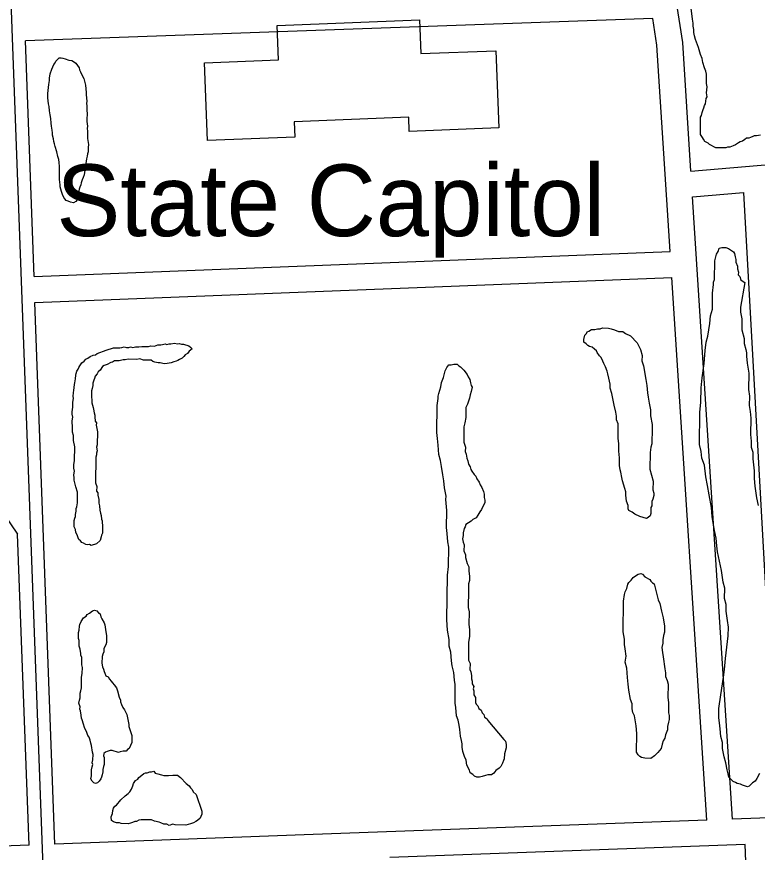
# Model space of a CAD drawing. Extents: x 3313447 to 3351316, y 703786 to 729172.
# Drawn here: x 3326436 to 3327294, y 710857 to 711825 of the extents above; entities that cross this region are included whole.
import ezdxf

# ---------------------------------------------------------------- set-up
doc = ezdxf.new("R2010")
doc.units = 0
for name, color, linetype in [('V-BLDG-IDEN', 7, 'Continuous'), ('V-BLDG-OTLN', 7, 'Continuous'), ('V-ROAD-CNTR', 7, 'Continuous'), ('V-SITE-VEGE', 7, 'Continuous')]:
    doc.layers.add(name, color=color, linetype=linetype)

msp = doc.modelspace()

# ---------------------------------------------------------------- linework, layer by layer
at = {"layer": 'V-BLDG-OTLN'}
msp.add_lwpolyline([(3326994.29, 711696.55), (3326890.49, 711692.54), (3326889.85, 711708.86), (3326757.17, 711703.73), (3326757.87, 711685.66), (3326656.79, 711682.07), (3326653.2, 711771.84), (3326739.21, 711775.4), (3326737.67, 711815.26), (3326902.5, 711821.64), (3326904.01, 711782.54), (3326990.83, 711785.9)], close=True, dxfattribs=at)
at = {"layer": 'V-ROAD-CNTR'}
for points in [[(3327216.9, 711646.58), (3327207.32, 711795.51), (3327188.59, 711916.24), (3327186.2, 712008.22)], [(3326425.23, 711947.61), (3326475.97, 710569.13), (3326516.02, 709785.48), (3326536.77, 709183.66)], [(3327172.64, 711823.37), (3326445.78, 711797.31)], [(3327192.84, 711553.28), (3327177.47, 711792.24), (3327172.64, 711823.37)], [(3326455.82, 711524.37), (3326445.78, 711797.31)], [(3327216.9, 711646.59), (3327551.72, 711675.17)], [(3327218.82, 711616.64), (3327277.6, 711621.66)], [(3327277.6, 711621.66), (3327317.84, 710897.83)], [(3327265.17, 710895.9), (3327218.82, 711616.64)], [(3326455.82, 711524.37), (3327192.84, 711553.28)], [(3326456.92, 711494.39), (3327194.76, 711523.34)], [(3327235.18, 710894.79), (3327194.76, 711523.34)], [(3326480.02, 710866.87), (3326456.92, 711494.39)], [(3326279.86, 711456.84), (3326436.78, 711226.09)], [(3326450.04, 710865.75), (3326436.78, 711226.09)], [(3327235.18, 710894.79), (3326768.62, 710877.65), (3326480.02, 710866.87)], [(3327317.84, 710897.83), (3327265.17, 710895.9)], [(3326450.04, 710865.75), (3326230.3, 710857.54)], [(3327279.69, 710866.41), (3326867.92, 710851.28)], [(3327288.74, 710639.67), (3327279.69, 710866.41)]]:
    msp.add_lwpolyline(points, dxfattribs=at)
at = {"layer": 'V-SITE-VEGE'}
for points in [[(3327297.49, 711688.1), (3327292.95, 711687.26), (3327290.23, 711687.3), (3327288.41, 711686.42), (3327285.68, 711685.55), (3327283.85, 711684.67), (3327281.14, 711684.7), (3327279.3, 711682.92), (3327276.56, 711681.14), (3327273.83, 711680.27), (3327272, 711679.39), (3327268.34, 711676.72), (3327265.61, 711675.86), (3327261.96, 711674.09), (3327259.24, 711674.13), (3327257.42, 711673.25), (3327245.64, 711673.41), (3327238.44, 711677.14), (3327236.66, 711678.97), (3327233.06, 711680.83), (3327231.28, 711683.58), (3327230.4, 711685.4), (3327227.73, 711689.06), (3327228.01, 711708.99), (3327228.94, 711710.79), (3327229.9, 711714.4), (3327230.85, 711718.01), (3327231.78, 711719.81), (3327232.72, 711722.52), (3327233.66, 711724.32), (3327234.65, 711730.64), (3327235.58, 711732.44), (3327234.73, 711736.99), (3327235.74, 711744.22), (3327234.89, 711747.86), (3327235.03, 711758.73), (3327234.18, 711762.36), (3327232.41, 711766.01), (3327230.69, 711772.38), (3327229.85, 711776.92), (3327228.1, 711781.48), (3327225.49, 711789.67), (3327221.99, 711798.78), (3327221.15, 711803.32), (3327220.29, 711806.95), (3327220.34, 711810.58), (3327219.48, 711814.21), (3327219.53, 711817.84), (3327218.69, 711822.38), (3327217.05, 711835.09)], [(3327244.11, 711230.24), (3327241.38, 711245.98), (3327240.55, 711256.8), (3327237.81, 711271.56), (3327235.99, 711282.38), (3327234.16, 711292.23), (3327232.39, 711305.99), (3327229.55, 711313.89), (3327228.68, 711321.76), (3327226.82, 711329.63), (3327227.33, 711366.94), (3327228.47, 711378.7), (3327228.7, 711395.39), (3327229.85, 711407.15), (3327232.04, 711423.82), (3327233.22, 711438.53), (3327234.34, 711448.33), (3327236.39, 711455.17), (3327238.56, 711469.87), (3327239.66, 711478.69), (3327241.73, 711486.52), (3327241.99, 711505.17), (3327243.1, 711514.97), (3327243.14, 711517.91), (3327244.17, 711520.84), (3327244.46, 711542.44), (3327245.51, 711547.34), (3327246.53, 711550.27), (3327248.54, 711553.19), (3327249.57, 711557.1), (3327252.53, 711558.04), (3327257.44, 711557.97), (3327260.37, 711556.95), (3327266.21, 711552.94), (3327267.16, 711550.96), (3327268.09, 711547.03), (3327269.03, 711544.07), (3327268.99, 711541.12), (3327270.88, 711536.19), (3327270.85, 711533.24), (3327271.77, 711529.3), (3327271.73, 711526.36), (3327273.67, 711524.37), (3327274.6, 711520.43), (3327277.51, 711518.42), (3327279.46, 711517.42), (3327274.17, 711489.02)], [(3327274.17, 711489.02), (3327274.08, 711483.13), (3327275.94, 711475.25), (3327275.77, 711462.49), (3327278.58, 711452.63), (3327278.5, 711446.74), (3327280.37, 711439.84), (3327281.29, 711435.9), (3327281.24, 711431.98), (3327282.11, 711424.11), (3327283.92, 711412.31), (3327283.66, 711393.65), (3327284.53, 711385.79), (3327284.39, 711374.99), (3327285.27, 711368.1), (3327286.15, 711360.24), (3327285.89, 711341.59), (3327286.77, 711333.72), (3327286.67, 711326.85), (3327288.55, 711320.94), (3327288.45, 711313.08), (3327290.22, 711299.31), (3327290.1, 711290.48), (3327290.96, 711281.63), (3327292.73, 711267.86), (3327294.58, 711259)], [(3326506.32, 711274.74), (3326504.34, 711280.95), (3326502.39, 711288.53), (3326502.42, 711291.28), (3326501.78, 711294.72), (3326502.52, 711298.84), (3326501.89, 711302.28), (3326501.94, 711306.4), (3326502.69, 711311.2), (3326502.91, 711327), (3326501.64, 711334.57), (3326501.71, 711340.06), (3326500.4, 711344.2), (3326500.5, 711351.76), (3326499.85, 711354.52), (3326499.89, 711357.26), (3326500.63, 711361.37), (3326500, 711364.82), (3326500.03, 711367.56), (3326500.79, 711373.05), (3326500.87, 711378.54), (3326501.62, 711383.34), (3326500.96, 711385.41), (3326501.71, 711390.21), (3326501.75, 711392.27), (3326502.48, 711395.69), (3326502.52, 711399.13), (3326503.24, 711401.18), (3326503.99, 711405.97), (3326504.05, 711410.1), (3326504.76, 711412.15), (3326505.49, 711414.89), (3326506.89, 711416.93), (3326507.6, 711418.98), (3326509.01, 711421.02), (3326511.12, 711424.43), (3326513.89, 711426.45), (3326515.98, 711428.48), (3326518.06, 711429.83), (3326520.83, 711431.85), (3326524.29, 711433.18), (3326527.04, 711433.83), (3326529.12, 711435.17), (3326539.48, 711439.15), (3326547.76, 711441.78), (3326555.31, 711441.68), (3326557.39, 711442.34), (3326560.14, 711442.99), (3326562.88, 711442.26), (3326565.62, 711442.23), (3326567.7, 711442.89), (3326570.43, 711442.16), (3326573.19, 711442.81), (3326577.31, 711442.75), (3326580.76, 711443.39), (3326588.31, 711443.29), (3326591.06, 711443.94), (3326595.19, 711443.88), (3326599.33, 711445.2), (3326602.76, 711445.15), (3326604.83, 711445.81), (3326607.59, 711446.46), (3326609.64, 711445.74), (3326612.39, 711446.39), (3326614.46, 711446.36), (3326618.58, 711447), (3326622.01, 711446.27), (3326624.08, 711446.92), (3326626.82, 711446.2), (3326628.88, 711446.17), (3326635.03, 711444.02), (3326637.07, 711442.62), (3326639.1, 711440.53), (3326635.63, 711437.83)], [(3326635.63, 711437.83), (3326633.54, 711435.11), (3326630.77, 711433.78), (3326629.37, 711431.74), (3326627.28, 711429.7), (3326624.51, 711428.37), (3326622.43, 711427.02), (3326620.36, 711426.36), (3326617.6, 711425.71), (3326614.84, 711424.38), (3326610.02, 711423.76), (3326607.27, 711423.11), (3326605.22, 711423.82), (3326601.79, 711424.56), (3326599.73, 711424.59), (3326595.62, 711425.33), (3326593.57, 711426.04), (3326591.53, 711427.45), (3326582.6, 711427.57), (3326578.5, 711429), (3326575.05, 711428.36), (3326564.75, 711428.5), (3326561.31, 711427.86), (3326559.25, 711427.89), (3326554.42, 711426.58), (3326548.93, 711426.66), (3326546.85, 711425.31), (3326544.78, 711424.65), (3326540.63, 711422.65), (3326537.18, 711421.32), (3326535.1, 711419.98), (3326532.29, 711415.89), (3326530.21, 711413.86), (3326528.8, 711411.82), (3326526.71, 711409.1), (3326525.98, 711406.36), (3326525.27, 711404.31), (3326523.84, 711400.9), (3326523.81, 711398.15), (3326523.07, 711394.72), (3326522.35, 711391.99), (3326522.25, 711385.12), (3326522.89, 711380.98), (3326522.85, 711378.24), (3326524.15, 711372.73), (3326524.8, 711370.66), (3326525.44, 711366.53), (3326526.08, 711363.77), (3326526.06, 711361.71), (3326526.68, 711356.89), (3326528.02, 711354.82), (3326527.98, 711352.07), (3326529.25, 711344.49), (3326529.05, 711329.39), (3326528.32, 711326.65), (3326528.95, 711322.52), (3326528.23, 711319.78), (3326528.2, 711317.72), (3326527.48, 711314.98), (3326527.07, 711285.45), (3326528.39, 711281.31), (3326528.31, 711275.81), (3326529.66, 711273.73), (3326529.62, 711270.99), (3326530.93, 711266.16), (3326530.87, 711262.04), (3326531.51, 711258.6), (3326532.13, 711253.78), (3326532.77, 711250.34), (3326533.42, 711247.58), (3326534.05, 711243.45), (3326534.71, 711241.38), (3326534.68, 711239.32), (3326535.32, 711235.88), (3326535.2, 711226.95), (3326533.8, 711224.91), (3326533.77, 711222.85), (3326532.34, 711218.74), (3326528.16, 711214.68), (3326521.95, 711212.7), (3326519.91, 711214.11), (3326517.84, 711213.45), (3326515.79, 711214.16), (3326513.06, 711215.57), (3326511.01, 711216.29), (3326509.67, 711218.37), (3326507.62, 711219.77), (3326506.96, 711221.84), (3326505.64, 711225.29), (3326504.3, 711228.06), (3326503.66, 711231.5), (3326502.33, 711234.27), (3326502.43, 711241.82), (3326503.16, 711244.56), (3326503.87, 711246.61), (3326503.9, 711248.67), (3326504.64, 711252.78), (3326504.68, 711255.53), (3326505.39, 711257.58), (3326506.15, 711262.38), (3326506.32, 711274.74)], [(3326999.96, 710988.25), (3327001.89, 710986.26), (3327002.82, 710982.32), (3327002.77, 710978.39), (3327000.71, 710971.55), (3327000.63, 710965.66), (3326999.62, 710963.7), (3326998.6, 710960.78), (3326996.58, 710956.88), (3326994.59, 710954.94), (3326990.63, 710952.05), (3326988.62, 710949.13), (3326985.65, 710947.21), (3326981.72, 710947.26), (3326978.77, 710946.32), (3326974.83, 710945.39), (3326971.87, 710944.45), (3326968.92, 710944.49), (3326965.99, 710945.52), (3326964.06, 710947.5), (3326961.14, 710949.51), (3326960.2, 710952.46), (3326957.33, 710958.4), (3326956.43, 710964.3), (3326954.52, 710968.25), (3326952.64, 710974.17), (3326951.72, 710979.09), (3326951.78, 710983.02), (3326950.85, 710986.96), (3326949.94, 710991.88), (3326949.06, 710999.75), (3326948.15, 711004.67), (3326947.25, 711010.57), (3326945.35, 711015.5), (3326944.5, 711025.33), (3326943.59, 711030.26), (3326943.88, 711051.85), (3326942.97, 711056.77), (3326942.11, 711065.62), (3326940.25, 711073.5), (3326939.35, 711079.4), (3326938.51, 711089.23), (3326936.64, 711096.13), (3326936.75, 711103.98), (3326934.93, 711114.81), (3326934.11, 711126.6), (3326934.82, 711178.63), (3326935.94, 711188.43), (3326936.25, 711211.01), (3326935.35, 711216.91), (3326934.5, 711226.74), (3326933.61, 711233.62), (3326933.88, 711253.26), (3326933.07, 711266.03), (3326933.13, 711269.96), (3326931.3, 711279.8), (3326930.43, 711287.67), (3326929.54, 711294.55), (3326927.71, 711304.39), (3326926.82, 711311.28), (3326924.95, 711318.18), (3326924.12, 711328.99), (3326923.25, 711336.85), (3326922.36, 711343.74), (3326922.79, 711375.15), (3326923.88, 711382.99), (3326923.92, 711385.94), (3326924.94, 711388.87), (3326927.01, 711396.69), (3326928.06, 711401.59), (3326930.1, 711407.45), (3326932.17, 711415.28), (3326934.19, 711419.17), (3326936.19, 711422.09), (3326939.14, 711422.05), (3326942.1, 711422.99), (3326946.02, 711422.94), (3326947.96, 711420.95), (3326949.91, 711419.94), (3326953.78, 711415.96), (3326957.64, 711411), (3326958.58, 711408.04), (3326960.51, 711405.07), (3326961.44, 711401.13), (3326962.38, 711398.17), (3326963.33, 711396.19), (3326962.28, 711391.3), (3326961.25, 711387.39), (3326960.21, 711383.47), (3326958.15, 711376.63), (3326956.14, 711372.73), (3326955.98, 711360.95), (3326954.91, 711355.07), (3326953.86, 711350.18), (3326953.62, 711332.51), (3326955.5, 711326.59), (3326955.44, 711321.69), (3326956.38, 711318.73), (3326957.29, 711313.81), (3326958.23, 711310.85), (3326959.16, 711306.91)], [(3326959.16, 711306.91), (3326961.08, 711303.94), (3326962.03, 711300.98), (3326962.98, 711299), (3326965.87, 711295.04), (3326967.81, 711293.04), (3326968.75, 711290.09), (3326971.64, 711286.12), (3326972.58, 711283.16), (3326974.5, 711280.19), (3326976.4, 711275.26), (3326977.34, 711272.3), (3326977.29, 711268.37), (3326978.23, 711265.41), (3326978.19, 711262.46), (3326974.15, 711254.66), (3326972.15, 711251.75), (3326970.13, 711247.85), (3326968.13, 711244.93), (3326964.18, 711243.02), (3326962.19, 711241.09), (3326956.24, 711237.24), (3326955.22, 711234.31), (3326954.21, 711232.36), (3326953.16, 711227.46), (3326953.12, 711224.52), (3326952.09, 711220.61), (3326953.02, 711216.67), (3326953.96, 711213.71), (3326953.86, 711206.84), (3326955.76, 711201.9), (3326955.72, 711198.96), (3326957.58, 711192.06), (3326959.49, 711188.11), (3326959.43, 711183.2), (3326960.33, 711177.3), (3326960.26, 711172.39), (3326959.23, 711168.47), (3326959.12, 711160.62), (3326958.85, 711140.99), (3326959.77, 711136.07), (3326959.56, 711121.34), (3326960.46, 711115.44), (3326960.36, 711107.59), (3326959.28, 711100.73), (3326959, 711080.11), (3326960.91, 711076.16), (3326960.81, 711069.29), (3326961.75, 711066.33), (3326962.68, 711062.39), (3326962.63, 711058.47), (3326963.57, 711055.51), (3326963.53, 711052.56), (3326965.45, 711049.59), (3326964.43, 711046.66), (3326965.39, 711044.68), (3326965.32, 711039.78), (3326967.24, 711036.8), (3326967.16, 711030.91), (3326968.12, 711028.94), (3326970.05, 711026.95), (3326970.99, 711023.99), (3326973.91, 711021.98), (3326974.85, 711019.03), (3326976.79, 711017.04), (3326977.73, 711014.08), (3326980.65, 711012.08), (3326981.6, 711010.1), (3326999.96, 710988.25)], [(3327296.22, 710948.73), (3327293.19, 710942.89), (3327291.19, 710939.97), (3327288.22, 710938.05), (3327284.23, 710934.17), (3327282.26, 710933.22), (3327276.4, 710935.26), (3327274.45, 710936.27), (3327270.53, 710937.31), (3327268.58, 710938.31), (3327265.65, 710939.34), (3327260.81, 710944.31), (3327259.89, 710948.25), (3327258.97, 710953.17), (3327257.11, 710961.06), (3327255.25, 710967.95), (3327253.42, 710977.79), (3327253.51, 710984.66), (3327251.64, 710991.56), (3327250.78, 711000.41), (3327249.89, 711007.3), (3327248.99, 711013.2), (3327249.14, 711024), (3327251.32, 711039.67), (3327254.54, 711060.25), (3327255.65, 711069.07), (3327256.8, 711081.82), (3327260.11, 711108.28), (3327260.25, 711118.1), (3327259.38, 711125.96), (3327257.56, 711136.78), (3327257.67, 711144.64), (3327255.8, 711151.54), (3327255.96, 711163.32), (3327254.09, 711170.21), (3327252.31, 711183.98), (3327247.7, 711205.65), (3327246.81, 711212.53), (3327245.95, 711221.38), (3327244.11, 711230.24)], [(3326537.79, 711064.8), (3326539.12, 711062.03), (3326541.85, 711060.62), (3326543.19, 711057.86), (3326545.22, 711055.77), (3326546.56, 711053.69), (3326548.6, 711051.6), (3326551.29, 711048.13), (3326552.62, 711044.68), (3326554.58, 711037.09), (3326555.9, 711033.64), (3326555.88, 711031.58), (3326557.21, 711028.81), (3326558.54, 711025.36), (3326560.56, 711022.58), (3326563.23, 711017.05), (3326565.82, 711005.34), (3326565.79, 711003.28), (3326569.08, 710992.93), (3326568.97, 710984.69), (3326566.14, 710977.86), (3326564.05, 710976.51), (3326562.65, 710974.47), (3326559.22, 710974.52), (3326555.77, 710973.88), (3326553.7, 710973.22), (3326546.18, 710975.38), (3326544.12, 710975.41), (3326540.67, 710974.09), (3326538.6, 710973.43), (3326536.52, 710972.08), (3326536.48, 710969.33), (3326537.14, 710967.26), (3326537.02, 710959.02), (3326536.31, 710956.97), (3326535.58, 710953.55), (3326535.54, 710950.8), (3326534.8, 710947.37), (3326534.08, 710944.64), (3326533.37, 710942.59), (3326531.27, 710939.87), (3326529.18, 710937.83), (3326527.11, 710937.18), (3326525.06, 710937.89), (3326523.02, 710939.98), (3326521.69, 710942.75), (3326522.42, 710946.17), (3326522.52, 710953.04), (3326523.25, 710956.46), (3326523.98, 710959.2), (3326523.31, 710961.27), (3326524.05, 710964.69), (3326524.13, 710970.88), (3326523.48, 710973.63), (3326522.22, 710981.2), (3326521.57, 710983.96), (3326520.92, 710987.41), (3326519.6, 710990.86), (3326518.25, 710992.94), (3326516.93, 710996.39), (3326514.26, 711001.92), (3326512.94, 711006.06), (3326511.63, 711010.89), (3326510.97, 711012.96), (3326510.33, 711016.4), (3326509.71, 711021.22), (3326509.05, 711023.29), (3326509.09, 711026.04), (3326507.77, 711030.18), (3326508.51, 711033.6), (3326509.23, 711036.34), (3326509.31, 711041.83), (3326510.03, 711044.57), (3326510.77, 711047.99), (3326510.93, 711060.36), (3326511.68, 711064.47), (3326511.77, 711071.34), (3326511.13, 711074.78), (3326511.25, 711083.02), (3326509.91, 711085.79), (3326509.94, 711087.85), (3326509.32, 711092.67), (3326507.99, 711096.12), (3326508.08, 711102.98), (3326507.43, 711105.06), (3326507.52, 711111.93), (3326508.24, 711114.66), (3326508.31, 711119.47), (3326509.03, 711121.52), (3326510.45, 711124.94), (3326513.25, 711129.02), (3326516.02, 711131.04), (3326517.43, 711133.08), (3326520.19, 711134.42), (3326523.67, 711137.12), (3326525.74, 711137.78), (3326528.47, 711137.06), (3326530.5, 711134.96), (3326532.55, 711133.56), (3326533.19, 711130.12), (3326534.53, 711128.04)], [(3326534.53, 711128.04), (3326537.21, 711123.2), (3326537.87, 711121.12), (3326538.48, 711115.62), (3326539.13, 711112.86), (3326539.76, 711108.73), (3326539.65, 711100.49), (3326538.93, 711097.76), (3326536.81, 711093.66), (3326536.75, 711089.54), (3326535.34, 711086.81), (3326534.62, 711084.07), (3326534.51, 711076.52), (3326535.14, 711072.39), (3326536.48, 711069.62), (3326537.13, 711066.87), (3326537.79, 711064.8)]]:
    msp.add_lwpolyline(points, dxfattribs=at)
for points in [[(3326517.69, 711692.59), (3326517.63, 711688.46), (3326517.92, 711684.32), (3326518.86, 711677.41), (3326518.47, 711673.97), (3326518.4, 711668.8), (3326517.67, 711666.4), (3326517.29, 711663.65), (3326516.56, 711660.56), (3326513.89, 711641.98), (3326512.82, 711639.23), (3326511.41, 711636.5), (3326510.33, 711633.06), (3326509.95, 711630.66), (3326508.88, 711627.91), (3326508.15, 711625.51), (3326507.41, 711621.38), (3326506.63, 711615.19), (3326505.92, 711613.13), (3326504.17, 711611.43), (3326501.39, 711609.75), (3326497.95, 711610.48), (3326495.21, 711611.56), (3326493.15, 711612.62), (3326491.46, 711614.36), (3326490.45, 711616.1), (3326488.77, 711619.57), (3326487.78, 711623.03), (3326486.13, 711628.23), (3326486.17, 711630.98), (3326485.51, 711633.4), (3326485.22, 711637.2), (3326485.42, 711651.67), (3326484.79, 711656.51), (3326484.5, 711659.96), (3326483.51, 711663.42), (3326482.21, 711668.95), (3326480.22, 711674.84), (3326479.57, 711677.95), (3326478.58, 711680.72), (3326478.28, 711683.83), (3326477.3, 711687.98), (3326477.34, 711690.73), (3326476.69, 711693.85), (3326476.07, 711698.68), (3326475.77, 711702.13), (3326475.15, 711707.31), (3326474.52, 711711.8), (3326473.55, 711716.3), (3326473.27, 711721.12), (3326472.62, 711724.24), (3326471.69, 711731.49), (3326471.76, 711736.31), (3326472.94, 711746.98), (3326473.69, 711751.45), (3326473.73, 711754.21), (3326474.48, 711759.02), (3326476.28, 711764.52), (3326477.69, 711767.25), (3326478.77, 711769.99), (3326480.17, 711771.7), (3326481.23, 711773.76), (3326482.98, 711775.8), (3326485.08, 711777.49), (3326487.15, 711777.81), (3326489.21, 711777.44), (3326491.95, 711776.36), (3326496.07, 711774.93), (3326499.51, 711774.54), (3326502.59, 711772.77), (3326504.29, 711771.37), (3326506.33, 711768.93), (3326508.01, 711766.15), (3326508.32, 711763.73), (3326509.68, 711761.65), (3326510.67, 711758.87), (3326513.36, 711753.67), (3326515.32, 711746.06), (3326516.24, 711737.43), (3326516.2, 711734.67), (3326516.79, 711727.42), (3326516.75, 711724.67), (3326517.06, 711721.9), (3326516.99, 711716.73), (3326517.29, 711713.28), (3326517.25, 711711.21), (3326516.87, 711708.12), (3326517.16, 711703.98), (3326517.77, 711698.45), (3326517.39, 711695.7)], [(3327172.92, 711287.29), (3327172.79, 711277.47), (3327173.72, 711273.53), (3327173.68, 711270.59), (3327172.64, 711266.67), (3327171.62, 711263.74), (3327171.55, 711258.83), (3327170.54, 711256.88), (3327170.45, 711250.02), (3327169.43, 711247.08), (3327167.44, 711245.15), (3327165.46, 711244.19), (3327157.63, 711246.26), (3327151.79, 711249.29), (3327148.87, 711251.29), (3327144.97, 711253.31), (3327144.01, 711255.29), (3327144.07, 711259.21), (3327142.17, 711264.15), (3327141.28, 711271.03), (3327141.34, 711274.96), (3327140.41, 711278.9), (3327137.59, 711287.77), (3327136.66, 711291.71), (3327135.76, 711297.61), (3327134.81, 711300.57), (3327133.9, 711305.5), (3327134.02, 711314.33), (3327133.15, 711322.2), (3327133.27, 711331.03), (3327132.37, 711336.93), (3327132.6, 711353.62), (3327130.7, 711358.56), (3327130.75, 711362.48), (3327129.84, 711367.41), (3327127.98, 711375.28), (3327126.16, 711385.13), (3327125.23, 711389.07), (3327123.35, 711394.98), (3327123.41, 711399.89), (3327121.54, 711406.79), (3327120.63, 711411.71), (3327119.69, 711414.67), (3327117.79, 711419.6), (3327115.88, 711423.56), (3327114.94, 711426.51), (3327113.03, 711430.47), (3327111.1, 711432.46), (3327108.21, 711436.43), (3327107.25, 711438.4), (3327105.31, 711440.39), (3327102.4, 711442.4), (3327099.46, 711443.42), (3327097.52, 711444.43), (3327095.58, 711446.42), (3327092.66, 711448.42), (3327092.7, 711451.36), (3327093.75, 711456.26), (3327095.74, 711458.2), (3327096.75, 711460.15), (3327098.73, 711461.1), (3327101.7, 711463.02), (3327105.62, 711462.97), (3327108.58, 711463.91), (3327111.52, 711463.87), (3327114.48, 711464.81), (3327121.36, 711464.72), (3327124.29, 711463.7), (3327128.2, 711462.66), (3327133.08, 711460.63), (3327137.99, 711460.56), (3327140.91, 711458.56), (3327146.76, 711455.53), (3327154.5, 711447.57), (3327158.32, 711439.67), (3327160.19, 711432.77), (3327160.11, 711426.88), (3327161.99, 711420.96), (3327164.72, 711405.22), (3327165.61, 711398.33), (3327166.47, 711389.48), (3327167.39, 711384.56), (3327168.27, 711377.68), (3327170.13, 711369.8), (3327170.03, 711362.93), (3327171.86, 711353.08), (3327171.79, 711348.18), (3327171.55, 711330.51), (3327170.52, 711326.59), (3327169.45, 711320.72), (3327169.19, 711301.08)], [(3327178.89, 711149.76), (3327180.8, 711145.8), (3327182.64, 711136.94), (3327184.5, 711129.06), (3327186.33, 711119.22), (3327186.23, 711112.35), (3327185.2, 711108.43), (3327184.15, 711103.54), (3327184.1, 711099.61), (3327183.05, 711094.72), (3327183.95, 711088.82), (3327184.86, 711083.89), (3327186.64, 711070.12), (3327187.55, 711065.2), (3327187.5, 711061.28), (3327189.4, 711056.34), (3327190.32, 711052.4), (3327190.11, 711036.7), (3327191.01, 711030.79), (3327190.85, 711019.01), (3327191.79, 711016.05), (3327191.72, 711011.15), (3327190.7, 711008.21), (3327189.65, 711003.32), (3327189.6, 710999.39), (3327187.55, 710993.53), (3327186.52, 710989.62), (3327184.51, 710986.7), (3327183.48, 710982.79), (3327182.43, 710977.89), (3327178.44, 710973.04), (3327174.45, 710969.17), (3327170.49, 710966.28), (3327163.62, 710966.37), (3327159.71, 710967.41), (3327157.75, 710968.41), (3327155.82, 710970.4), (3327153.89, 710973.38), (3327154.19, 710994.97), (3327153.33, 711003.82), (3327151.53, 711015.63), (3327149.62, 711019.58), (3327148.69, 711023.52), (3327148.77, 711029.41), (3327146.88, 711034.34), (3327145.06, 711045.17), (3327144.18, 711052.05), (3327143.3, 711059.92), (3327142.47, 711070.73), (3327140.6, 711077.63), (3327141.67, 711084.49), (3327140.81, 711093.33), (3327139.9, 711098.25), (3327139.98, 711104.15), (3327138.14, 711113), (3327138.62, 711148.34), (3327139.71, 711156.18), (3327140.73, 711159.11), (3327142.75, 711163.01), (3327143.8, 711167.91), (3327144.81, 711169.86), (3327147.79, 711172.76), (3327149.79, 711175.68), (3327153.76, 711178.57), (3327155.74, 711179.53), (3327158.7, 711180.47), (3327160.65, 711179.46), (3327163.55, 711176.47), (3327169.4, 711173.45), (3327170.35, 711171.47), (3327172.29, 711169.48), (3327174.24, 711168.47), (3327175.18, 711165.52)], [(3326650.32, 710905.26), (3326650.27, 710901.83), (3326648.86, 710899.1), (3326648.15, 710897.05), (3326645.36, 710894.34), (3326643.28, 710893), (3326640.51, 710891.66), (3326637.06, 710890.33), (3326631.55, 710889.04), (3326619.18, 710889.2), (3326616.45, 710889.93), (3326612.31, 710888.61), (3326609.58, 710890.02), (3326606.15, 710890.07), (3326602.73, 710891.49), (3326600.68, 710892.2), (3326595.2, 710893.65), (3326591.79, 710895.07), (3326580.11, 710895.23), (3326577.36, 710894.58), (3326574.59, 710893.25), (3326572.53, 710893.28), (3326569.76, 710891.94), (3326567.69, 710891.28), (3326564.94, 710890.63), (3326556.7, 710890.75), (3326554.65, 710891.46), (3326551.21, 710891.51), (3326547.79, 710892.93), (3326545.75, 710894.33), (3326545.12, 710898.46), (3326546.55, 710902.56), (3326547.29, 710905.99), (3326548.01, 710908.73), (3326549.42, 710910.77), (3326551.49, 710912.11), (3326556.39, 710918.23), (3326561.26, 710922.97), (3326564.73, 710925.67), (3326566.82, 710927.7), (3326568.92, 710930.42), (3326570.35, 710934.52), (3326571.07, 710937.26), (3326573.18, 710940.67), (3326575.94, 710942), (3326577.35, 710944.04), (3326580.82, 710946.74), (3326582.91, 710948.78), (3326584.98, 710949.44), (3326587.04, 710949.41), (3326589.8, 710950.74), (3326591.86, 710950.71), (3326594.62, 710951.36), (3326595.97, 710949.29), (3326599.39, 710948.55), (3326603.49, 710947.12), (3326606.23, 710946.4), (3326611.73, 710946.32), (3326616.54, 710946.94), (3326622.04, 710946.87), (3326625.43, 710944.07), (3326632.21, 710937.11), (3326635.6, 710934.32), (3326636.95, 710932.23), (3326638.98, 710930.15), (3326640.31, 710927.38), (3326643.71, 710924.59)]]:
    msp.add_lwpolyline(points, close=True, dxfattribs=at)

# ---------------------------------------------------------------- texts
at = {"layer": 'V-BLDG-IDEN'}
msp.add_text('State Capitol', height=82.9998, dxfattribs=at).set_placement((3326481.7, 711571.17))

doc.saveas('drawing.dxf')
